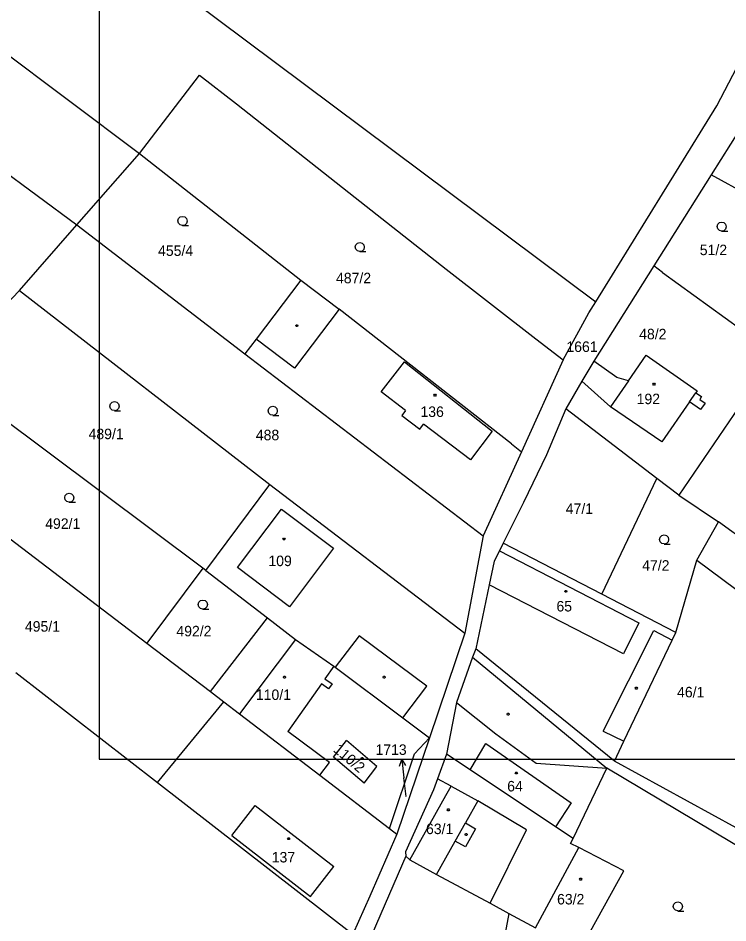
# Model space of a CAD drawing. Extents: x -802857 to -799647, y -1020285 to -1015884.
# Drawn here: x -801717 to -801601.9, y -1017640.2 to -1017493.5 of the extents above; entities that cross this region are included whole.
import ezdxf

# ---------------------------------------------------------------- set-up
doc = ezdxf.new("R2010")
doc.units = 0
for name, color, linetype in [('Default', 7, 'Continuous'), ('KN_HRANICE', 7, 'Continuous'), ('KN_KULTURY', 7, 'Continuous'), ('KN_PARCELY', 7, 'Continuous'), ('KN_SLUCKY', 7, 'Continuous'), ('LEGENDA', 7, 'Continuous')]:
    doc.layers.add(name, color=color, linetype=linetype)

# ---------------------------------------------------------------- blocks, each defined once
blk = doc.blocks.new('304')
at = {"layer": 'Default'}
blk.add_lwpolyline([(0, 0), (-0.38, 0.1), (-0.65, 0.37), (-0.75, 0.74), (-0.65, 1.11), (-0.38, 1.38), (-0.01, 1.48), (0.36, 1.38), (0.63, 1.11), (0.73, 0.73), (0.63, 0.35), (0.36, 0.08), (-0.02, -0.02), (0.98, -0.02)], dxfattribs=at)
blk = doc.blocks.new('10292')
at = {"layer": 'Default'}
blk.add_line((0, 3), (0, 0), dxfattribs=at)
blk.add_lwpolyline([(-0.5, 2), (0, 3), (0.5, 2)], dxfattribs=at)
blk = doc.blocks.new('402')
at = {"layer": 'Default'}
blk.add_lwpolyline([(0.09, 0.15), (0.18, 0), (0.09, -0.15), (-0.09, -0.15), (-0.18, 0), (-0.09, 0.15), (0.09, 0.15)], dxfattribs=at)

msp = doc.modelspace()

# ---------------------------------------------------------------- linework, layer by layer
at = {"layer": 'KN_HRANICE'}
for p, q in [((-801752.52, -1017442.84), (-801623.34, -1017539.52)), ((-801768.75, -1017461.94), (-801697.3, -1017515.42)), ((-801779.08, -1017474.09), (-801707.48, -1017527.01)), ((-801603.69, -1017507.7), (-801595.69, -1017492.25)), ((-801697.3, -1017515.42), (-801687.56, -1017502.76)), ((-801687.56, -1017502.76), (-801681.57, -1017507.37)), ((-801681.57, -1017507.37), (-801662.34, -1017522.59)), ((-801623.34, -1017539.52), (-801603.69, -1017507.7)), ((-801599.92, -1017511.43), (-801604.62, -1017518.91)), ((-801707.48, -1017527.01), (-801697.3, -1017515.42)), ((-801697.3, -1017515.42), (-801671.15, -1017535.99)), ((-801604.62, -1017518.91), (-801613.91, -1017533.68)), ((-801586.4, -1017528.88), (-801604.62, -1017518.91)), ((-801662.34, -1017522.59), (-801647.61, -1017534.21)), ((-801716.78, -1017537.68), (-801707.48, -1017527.01)), ((-801707.48, -1017527.01), (-801680.21, -1017547.94)), ((-801647.61, -1017534.21), (-801633.05, -1017545.52)), ((-801613.91, -1017533.68), (-801623.67, -1017549.1)), ((-801612.51, -1017534.74), (-801613.91, -1017533.68)), ((-801612.51, -1017534.74), (-801599.81, -1017543.92)), ((-801671.15, -1017535.99), (-801678.4, -1017545.55)), ((-801671.15, -1017535.99), (-801664.95, -1017540.69)), ((-801729.49, -1017550.94), (-801716.78, -1017537.68)), ((-801716.78, -1017537.68), (-801676.19, -1017569.11)), ((-801624.44, -1017541.3), (-801623.34, -1017539.52)), ((-801637, -1017562.55), (-801664.95, -1017540.69)), ((-801628.6, -1017548.89), (-801624.44, -1017541.3)), ((-801678.4, -1017545.55), (-801680.21, -1017547.94)), ((-801633.05, -1017545.52), (-801628.6, -1017548.89)), ((-801680.21, -1017547.94), (-801641.61, -1017577.47)), ((-801594.29, -1017547.96), (-801609.85, -1017570.88)), ((-801628.6, -1017548.89), (-801635.4, -1017563.83)), ((-801623.67, -1017549.1), (-801625.57, -1017552.36)), ((-801619.9, -1017551.8), (-801623.67, -1017549.1)), ((-801618.03, -1017552.3), (-801615.19, -1017548.14)), ((-801615.19, -1017548.14), (-801606.91, -1017553.95)), ((-801687.03, -1017582.73), (-801729.49, -1017550.94)), ((-801625.57, -1017552.36), (-801628.2, -1017556.86)), ((-801625.57, -1017552.36), (-801620.96, -1017556.51)), ((-801618.03, -1017552.3), (-801619.9, -1017551.8)), ((-801606.91, -1017553.95), (-801607.11, -1017554.24)), ((-801607.11, -1017554.24), (-801606.18, -1017554.88)), ((-801606.18, -1017554.88), (-801606.48, -1017555.33)), ((-801612.65, -1017562.22), (-801620.96, -1017556.51)), ((-801608.14, -1017555.73), (-801612.65, -1017562.22)), ((-801606.34, -1017556.98), (-801608.14, -1017555.73)), ((-801606.48, -1017555.33), (-801605.61, -1017555.93)), ((-801605.61, -1017555.93), (-801606.34, -1017556.98)), ((-801628.2, -1017556.86), (-801631.32, -1017564.34)), ((-801613.44, -1017568.14), (-801628.2, -1017556.86)), ((-801637, -1017562.55), (-801635.4, -1017563.83)), ((-801737.57, -1017563.21), (-801696.11, -1017594.87)), ((-801635.4, -1017563.83), (-801641.61, -1017577.47)), ((-801631.32, -1017564.34), (-801635.08, -1017572.03)), ((-801622.34, -1017586.91), (-801613.44, -1017568.14)), ((-801609.85, -1017570.88), (-801613.44, -1017568.14)), ((-801686.57, -1017583.08), (-801676.19, -1017569.11)), ((-801676.19, -1017569.11), (-801644.59, -1017593.25)), ((-801609.85, -1017570.88), (-801603.42, -1017575.18)), ((-801635.08, -1017572.03), (-801638.36, -1017578.66)), ((-801606.97, -1017581.38), (-801603.42, -1017575.18)), ((-801593.16, -1017582.7), (-801603.42, -1017575.18)), ((-801641.61, -1017577.47), (-801644.59, -1017593.25)), ((-801638.36, -1017578.66), (-801638.97, -1017579.89)), ((-801622.34, -1017586.91), (-801638.36, -1017578.66)), ((-801638.97, -1017579.89), (-801639.81, -1017581.56)), ((-801639.81, -1017581.56), (-801640.61, -1017585.38)), ((-801610.33, -1017593.16), (-801606.97, -1017581.38)), ((-801606.97, -1017581.38), (-801591.28, -1017593.15)), ((-801687.03, -1017582.73), (-801696.11, -1017594.87)), ((-801686.57, -1017583.08), (-801687.03, -1017582.73)), ((-801686.57, -1017583.08), (-801676.56, -1017590.77)), ((-801640.61, -1017585.38), (-801642.78, -1017595.77)), ((-801610.33, -1017593.16), (-801622.34, -1017586.91)), ((-801685.82, -1017602.73), (-801676.56, -1017590.77)), ((-801676.56, -1017590.77), (-801672.03, -1017594.25)), ((-801644.59, -1017593.25), (-801650.28, -1017610.24)), ((-801610.94, -1017594.36), (-801610.33, -1017593.16)), ((-801696.11, -1017594.87), (-801685.82, -1017602.73)), ((-801672.03, -1017594.25), (-801665.81, -1017598.61)), ((-801618.76, -1017610.78), (-801610.94, -1017594.36)), ((-801642.78, -1017595.77), (-801643.3, -1017597.13)), ((-801620.3, -1017614.03), (-801642.78, -1017595.77)), ((-801643.3, -1017597.13), (-801645.9, -1017604.47)), ((-801643.3, -1017597.13), (-801621.52, -1017615.14)), ((-801665.81, -1017598.61), (-801665.58, -1017598.77)), ((-801665.58, -1017598.77), (-801654.61, -1017606.97)), ((-801717.38, -1017599.65), (-801694.39, -1017617.48)), ((-801685.82, -1017602.73), (-801683.64, -1017604.39)), ((-801694.39, -1017617.48), (-801683.64, -1017604.39)), ((-801683.64, -1017604.39), (-801681.1, -1017606.33)), ((-801645.9, -1017604.47), (-801647.52, -1017612.87)), ((-801681.1, -1017606.33), (-801668.08, -1017616.3)), ((-801654.61, -1017606.97), (-801650.28, -1017610.24)), ((-801665.85, -1017613.34), (-801663.76, -1017610.64)), ((-801658.81, -1017614.87), (-801663.76, -1017610.64)), ((-801650.28, -1017610.24), (-801655.61, -1017625.85)), ((-801652.74, -1017612.84), (-801650.28, -1017610.24)), ((-801620.3, -1017614.03), (-801618.76, -1017610.78)), ((-801660.9, -1017617.57), (-801665.85, -1017613.34)), ((-801656.8, -1017624.94), (-801652.74, -1017612.84)), ((-801647.52, -1017612.87), (-801649.02, -1017616.9)), ((-801643.72, -1017615.4), (-801647.52, -1017612.87)), ((-801660.9, -1017617.57), (-801658.81, -1017614.87)), ((-801629.84, -1017624.66), (-801643.72, -1017615.4)), ((-801627, -1017626.55), (-801621.52, -1017615.14)), ((-801584.1, -1017637.52), (-801621.52, -1017615.14)), ((-801600.56, -1017624.82), (-801620.3, -1017614.03)), ((-801668.08, -1017616.3), (-801656.8, -1017624.94)), ((-801649.02, -1017616.9), (-801649.67, -1017618.65)), ((-801646.79, -1017618.07), (-801649.02, -1017616.9)), ((-801694.39, -1017617.48), (-801662.74, -1017642.08)), ((-801646.79, -1017618.07), (-801642.46, -1017620.47)), ((-801649.67, -1017618.65), (-801654.18, -1017628.7)), ((-801634.57, -1017625.14), (-801642.46, -1017620.47)), ((-801656.8, -1017624.94), (-801655.61, -1017625.85)), ((-801640.48, -1017637.07), (-801634.57, -1017625.14)), ((-801627, -1017626.55), (-801629.84, -1017624.66)), ((-801655.61, -1017625.85), (-801659.97, -1017635.92)), ((-801627.46, -1017627.34), (-801627, -1017626.55)), ((-801626.1, -1017628.02), (-801627.46, -1017627.34)), ((-801618.78, -1017631.82), (-801626.1, -1017628.02)), ((-801654.11, -1017629.4), (-801671.57, -1017669.41)), ((-801654.18, -1017628.7), (-801654.11, -1017629.4)), ((-801654.11, -1017629.4), (-801653.46, -1017630.01)), ((-801653.46, -1017630.01), (-801649.18, -1017632.41)), ((-801649.18, -1017632.41), (-801640.48, -1017637.07)), ((-801626.01, -1017644.85), (-801618.78, -1017631.82)), ((-801659.97, -1017635.92), (-801662.74, -1017642.08)), ((-801640.48, -1017637.07), (-801637.41, -1017638.71)), ((-801637.41, -1017638.71), (-801642.23, -1017664.46)), ((-801637.41, -1017638.71), (-801633.09, -1017641.02))]:
    msp.add_line(p, q, dxfattribs=at)
at = {"layer": 'KN_PARCELY'}
msp.add_line((-801654.08, -1017619.74), (-801654.44, -1017616.74), dxfattribs=at)
at = {"layer": 'KN_SLUCKY'}
for p, q in [((-801664.95, -1017540.69), (-801672.2, -1017550.25)), ((-801672.2, -1017550.25), (-801678.4, -1017545.55)), ((-801658.14, -1017554.09), (-801654.37, -1017549.26)), ((-801654.37, -1017549.26), (-801640.11, -1017560.46)), ((-801618.03, -1017552.3), (-801620.96, -1017556.51)), ((-801654.16, -1017557.12), (-801658.14, -1017554.09)), ((-801608.14, -1017555.73), (-801607.11, -1017554.24)), ((-801654.16, -1017557.12), (-801654.77, -1017557.92)), ((-801654.77, -1017557.92), (-801651.87, -1017560.13)), ((-801651.87, -1017560.13), (-801651.26, -1017559.33)), ((-801643.64, -1017565.14), (-801651.26, -1017559.33)), ((-801640.11, -1017560.46), (-801643.64, -1017565.14)), ((-801681.41, -1017582.62), (-801674.28, -1017573.12)), ((-801674.28, -1017573.12), (-801665.84, -1017579.45)), ((-801665.84, -1017579.45), (-801672.97, -1017588.95)), ((-801638.97, -1017579.89), (-801616.34, -1017591.55)), ((-801672.97, -1017588.95), (-801681.41, -1017582.62)), ((-801618.86, -1017596.61), (-801640.61, -1017585.38)), ((-801616.34, -1017591.55), (-801618.86, -1017596.61)), ((-801622.14, -1017609.12), (-801613.91, -1017592.8)), ((-801613.91, -1017592.8), (-801610.94, -1017594.36)), ((-801672.03, -1017594.25), (-801681.1, -1017606.33)), ((-801661.69, -1017593.67), (-801665.58, -1017598.77)), ((-801650.72, -1017601.82), (-801661.69, -1017593.67)), ((-801665.81, -1017598.61), (-801667.24, -1017600.66)), ((-801667.24, -1017600.66), (-801666.09, -1017601.46)), ((-801667.81, -1017601.48), (-801673.24, -1017609.22)), ((-801666.67, -1017602.28), (-801667.81, -1017601.48)), ((-801666.09, -1017601.46), (-801666.67, -1017602.28)), ((-801654.61, -1017606.97), (-801650.72, -1017601.82)), ((-801645.9, -1017604.47), (-801639.55, -1017609.58)), ((-801666.53, -1017614.22), (-801673.24, -1017609.22)), ((-801639.55, -1017609.58), (-801633.02, -1017614.35)), ((-801622.14, -1017609.12), (-801618.76, -1017610.78)), ((-801643.72, -1017615.4), (-801641.15, -1017611.16)), ((-801641.15, -1017611.16), (-801627.34, -1017620.77)), ((-801668.08, -1017616.3), (-801666.53, -1017614.22)), ((-801633.02, -1017614.35), (-801621.52, -1017615.14)), ((-801647.62, -1017619.56), (-801646.79, -1017618.07)), ((-801653.46, -1017630.01), (-801647.62, -1017619.56)), ((-801682.34, -1017626.05), (-801678.56, -1017621.22)), ((-801678.56, -1017621.22), (-801665.82, -1017631.12)), ((-801642.46, -1017620.47), (-801644.46, -1017624.03)), ((-801627.34, -1017620.77), (-801629.84, -1017624.66)), ((-801646.11, -1017626.96), (-801644.46, -1017624.03)), ((-801644.46, -1017624.03), (-801642.81, -1017624.96)), ((-801642.81, -1017624.96), (-801644.45, -1017627.89)), ((-801682.34, -1017626.05), (-801669.6, -1017635.95)), ((-801649.18, -1017632.41), (-801646.11, -1017626.96)), ((-801644.45, -1017627.89), (-801646.11, -1017626.96)), ((-801633.09, -1017641.02), (-801626.1, -1017628.02)), ((-801669.6, -1017635.95), (-801665.82, -1017631.12))]:
    msp.add_line(p, q, dxfattribs=at)
at = {"layer": 'LEGENDA'}
msp.add_lwpolyline([(-801703.84, -1017613.71), (-800862.84, -1017613.71), (-800862.84, -1017019.71), (-801703.84, -1017019.71)], close=True, dxfattribs=at)

# ---------------------------------------------------------------- block references
at = {"layer": 'KN_KULTURY'}
for name, p in [('304', (-801690.33, -1017527.12)), ('304', (-801602.91, -1017528.04)), ('304', (-801661.59, -1017531.34)), ('402', (-801671.8, -1017543.37)), ('402', (-801613.91, -1017552.86)), ('402', (-801649.39, -1017554.63)), ('304', (-801701.36, -1017557.15)), ('304', (-801675.7, -1017557.91)), ('304', (-801708.69, -1017572)), ('304', (-801612.25, -1017578.78)), ('402', (-801673.9, -1017577.98)), ('402', (-801628.19, -1017586.46)), ('304', (-801687.03, -1017589.35)), ('402', (-801673.8, -1017600.38)), ('402', (-801657.65, -1017600.38)), ('402', (-801616.75, -1017602.17)), ('402', (-801637.54, -1017606.39)), ('402', (-801661.21, -1017613.54)), ('402', (-801636.2, -1017615.92)), ('402', (-801647.25, -1017621.89)), ('402', (-801673.11, -1017626.57)), ('402', (-801644.34, -1017625.91)), ('402', (-801625.79, -1017633.15)), ('304', (-801610.02, -1017638.3))]:
    msp.add_blockref(name, p, dxfattribs=at)
at = {"layer": 'KN_PARCELY', "rotation": 6.875494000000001}
msp.add_blockref('10292', (-801654.44, -1017616.74), dxfattribs=at)

# ---------------------------------------------------------------- texts
at = {"layer": 'KN_PARCELY'}
for s, height, p in [('455/4', 1.7, (-801694.3, -1017532.05)), ('51/2', 1.7, (-801606.47, -1017531.93)), ('487/2', 1.7, (-801665.45, -1017536.49)), ('48/2', 1.7, (-801616.3, -1017545.58)), ('1661', 1.7, (-801628.1, -1017547.63)), ('192', 1.7, (-801616.71, -1017556.1)), ('136', 1.7, (-801651.76, -1017558.17)), ('489/1', 1.7, (-801705.57, -1017561.78)), ('488', 1.7, (-801678.45, -1017561.95)), ('47/1', 1.7, (-801628.2, -1017573.9)), ('492/1', 1.7, (-801712.6, -1017576.33)), ('109', 1.7, (-801676.41, -1017582.37)), ('47/2', 1.7, (-801615.81, -1017583.11)), ('65', 1.7, (-801629.71, -1017589.73)), ('495/1', 1.7, (-801715.89, -1017593)), ('492/2', 1.7, (-801691.33, -1017593.76)), ('46/1', 1.7, (-801610.15, -1017603.66)), ('110/1', 1.7, (-801678.44, -1017604.08)), ('1713', 1.7, (-801659.05, -1017612.99)), ('64', 1.7, (-801637.7, -1017618.92)), ('1713', 0.1, (-801654.28, -1017619.74)), ('63/1', 1.7, (-801650.86, -1017625.84)), ('137', 1.7, (-801675.87, -1017630.44)), ('63/2', 1.7, (-801629.61, -1017637.25))]:
    msp.add_text(s, height=height, dxfattribs=at).set_placement(p)
msp.add_text('110/2', height=1.7, rotation=319.882, dxfattribs=at).set_placement((-801666.01, -1017612.35))

doc.saveas('drawing.dxf')
